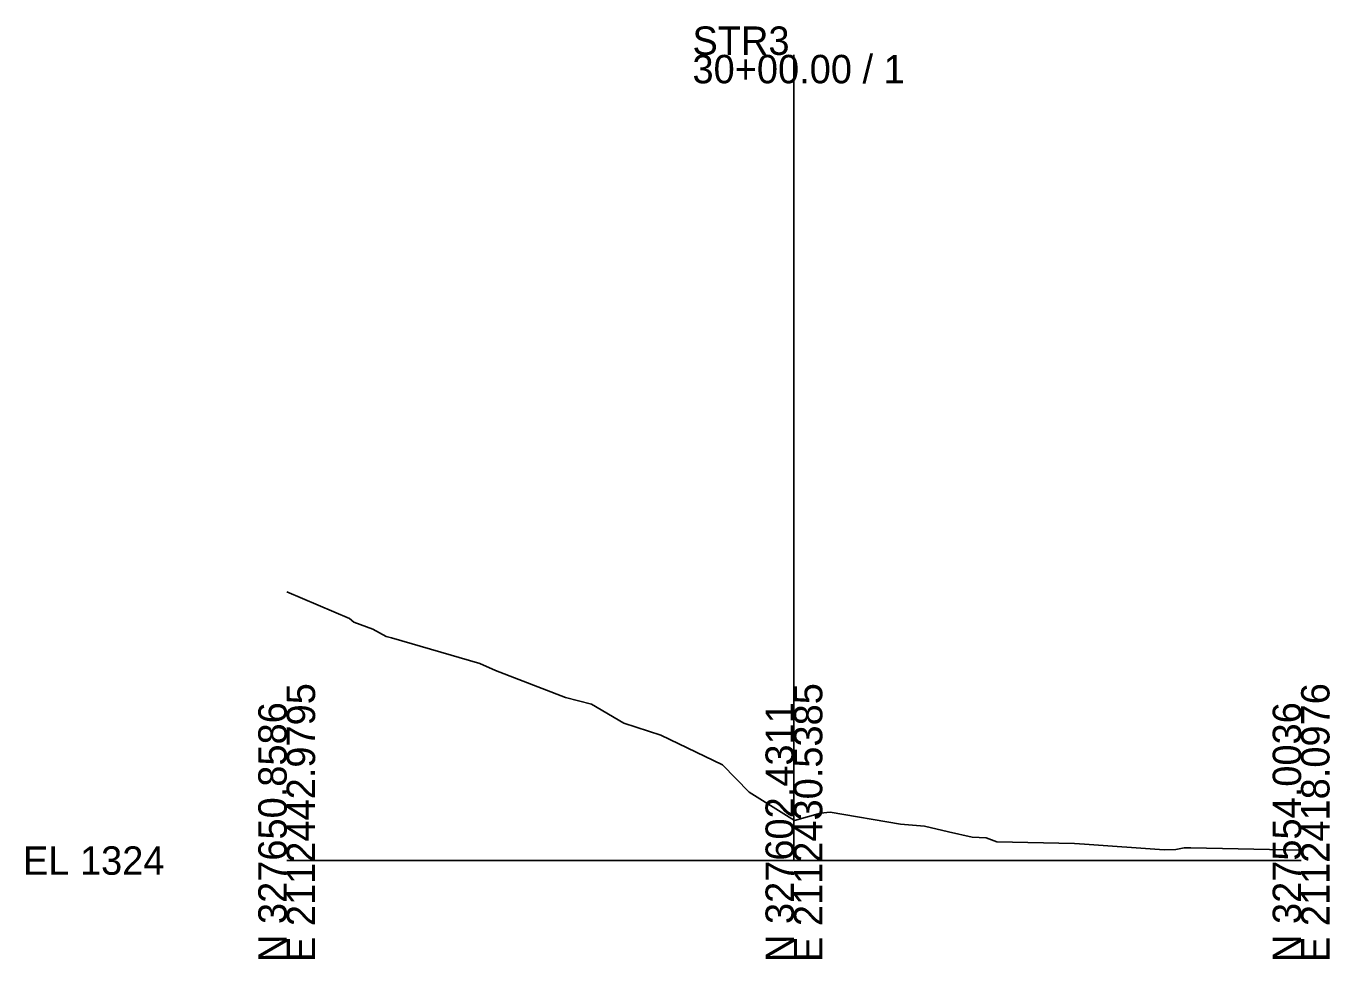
# Model space of a CAD drawing. Extents: x -26 to 103, y -10 to 14542.
# Drawn here: x -25.7 to 102.8, y -9.7 to 82.2 of the extents above; entities that cross this region are included whole.
import ezdxf

# ---------------------------------------------------------------- set-up
doc = ezdxf.new("R2010")
doc.units = 0
doc.layers.add('DESIGN - SHEET - Light Grid', color=7, linetype='Continuous')
doc.layers.add('SURVEY - GROUND - Top of Ground', color=7, linetype='Continuous')

msp = doc.modelspace()

# ---------------------------------------------------------------- linework, layer by layer
at = {"layer": 'DESIGN - SHEET - Light Grid'}
for p, q in [((50, 0), (50, 79.4)), ((0, 0), (50, 0)), ((50, 0), (100, 0))]:
    msp.add_line(p, q, dxfattribs=at)
at = {"layer": 'SURVEY - GROUND - Top of Ground'}
for p, q in [((0, 26.47), (6.18, 23.84)), ((6.18, 23.84), (6.61, 23.5)), ((6.61, 23.5), (8.49, 22.79)), ((8.49, 22.79), (9.82, 22.09)), ((9.82, 22.09), (10.33, 21.94)), ((10.33, 21.94), (19.04, 19.42)), ((19.04, 19.42), (20.59, 18.72)), ((20.59, 18.72), (27.47, 16.08)), ((27.47, 16.08), (30.05, 15.41)), ((30.05, 15.41), (33.25, 13.55)), ((33.25, 13.55), (36.88, 12.37)), ((36.88, 12.37), (42.96, 9.43)), ((42.96, 9.43), (45.6, 6.73)), ((45.6, 6.73), (50.07, 3.96)), ((50.07, 3.96), (52.63, 4.68)), ((52.63, 4.68), (53.58, 4.78)), ((53.58, 4.78), (60.52, 3.59)), ((60.52, 3.59), (62.86, 3.4)), ((62.86, 3.4), (65.23, 2.82)), ((65.23, 2.82), (67.57, 2.32)), ((67.57, 2.32), (68.96, 2.24)), ((68.96, 2.24), (70, 1.83)), ((70, 1.83), (77.65, 1.67)), ((77.65, 1.67), (78.64, 1.61)), ((78.64, 1.61), (86.51, 1.06)), ((86.51, 1.06), (87.64, 1.09)), ((87.64, 1.09), (88.46, 1.26)), ((88.46, 1.26), (89.13, 1.25)), ((89.13, 1.25), (100, 1.03))]:
    msp.add_line(p, q, dxfattribs=at)

# ---------------------------------------------------------------- texts
at = {"layer": 'DESIGN - SHEET - Light Grid'}
for s, p in [('STR3', (40, 79.4)), ('30+00.00 / 1', (40, 76.6)), ('EL 1324', (-26, -1.4))]:
    msp.add_text(s, height=2.8, dxfattribs=at).set_placement(p)
for s, p in [('E 2112442.9795', (2.8, -10)), ('E 2112430.5385', (52.8, -10)), ('E 2112418.0976', (102.8, -10)), ('N 327650.8586', (0, -10)), ('N 327602.4311', (50, -10)), ('N 327554.0036', (100, -10))]:
    msp.add_text(s, height=2.8, rotation=90, dxfattribs=at).set_placement(p)

doc.saveas('drawing.dxf')
